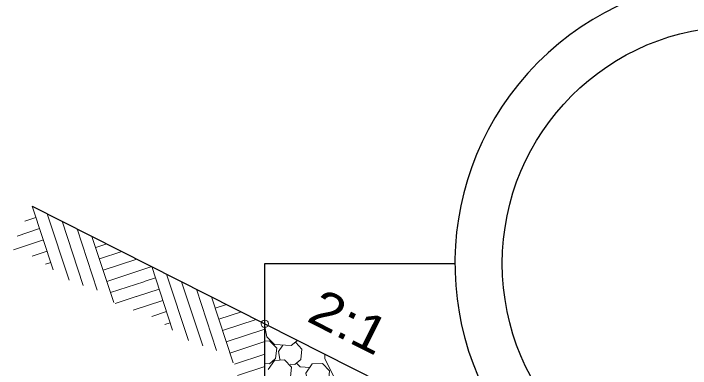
# Model space of a CAD drawing. Extents: x 685.4 to 719.4, y 1059.8 to 1105.8.
# Drawn here: x 692.638 to 695.494, y 1078.299 to 1079.794 of the extents above; entities that cross this region are included whole.
import ezdxf

# ---------------------------------------------------------------- set-up
doc = ezdxf.new("R2010")
doc.units = 0
doc.header["$LTSCALE"] = 0.062
doc.header["$PDMODE"] = 32
doc.header["$PDSIZE"] = 0.031
doc.layers.add('1', color=7, linetype='Continuous', lineweight=13)

msp = doc.modelspace()

# ---------------------------------------------------------------- linework, layer by layer
at = {"layer": '1'}
for p, q in [((692.71692, 1078.98283), (692.80517, 1078.71458)), ((692.68508, 1078.91983), (692.7325, 1078.93542)), ((692.77992, 1078.951), (692.872, 1078.67083)), ((692.84283, 1078.91917), (692.93192, 1078.6485)), ((692.65317, 1078.85675), (692.74817, 1078.888)), ((692.906, 1078.88733), (692.99075, 1078.62942)), ((692.638, 1078.79925), (692.76375, 1078.84058)), ((692.969, 1078.8555), (693.06058, 1078.57692)), ((692.98458, 1078.80808), (693.03192, 1078.82367)), ((692.71683, 1078.77258), (692.77933, 1078.79317)), ((693.00017, 1078.76058), (693.09508, 1078.79183)), ((693.01575, 1078.71325), (693.15808, 1078.76)), ((692.77267, 1078.7385), (692.79492, 1078.74583)), ((693.03133, 1078.66583), (693.221, 1078.72825)), ((693.221, 1078.72825), (693.30925, 1078.46)), ((693.284, 1078.69642), (693.37608, 1078.41617)), ((693.18917, 1078.66525), (693.23658, 1078.68083)), ((693.04692, 1078.61842), (693.18733, 1078.66458)), ((693.34692, 1078.66458), (693.436, 1078.39392)), ((693.15733, 1078.60217), (693.25225, 1078.63325)), ((693.41008, 1078.63267), (693.49492, 1078.37483)), ((693.06642, 1078.57225), (693.1555, 1078.60142)), ((693.14225, 1078.54458), (693.26783, 1078.58592)), ((693.47308, 1078.60083), (693.56467, 1078.32225)), ((693.48867, 1078.5535), (693.536, 1078.56908)), ((693.22092, 1078.518), (693.28342, 1078.5385)), ((693.50433, 1078.506), (693.59917, 1078.53717)), ((693.51983, 1078.45867), (693.66217, 1078.50533)), ((693.27675, 1078.48383), (693.299, 1078.49108)), ((693.53542, 1078.41125), (693.69792, 1078.46458)), ((693.551, 1078.36383), (693.69792, 1078.41217)), ((693.75533, 1078.37092), (693.77367, 1078.397)), ((693.57058, 1078.31767), (693.69792, 1078.3595)), ((693.58325, 1078.26925), (693.69792, 1078.307))]:
    msp.add_line(p, q, dxfattribs=at)
at = {"layer": '1', "lineweight": 25}
for p, q in [((693.69792, 1077.09492), (693.69792, 1078.741)), ((693.69792, 1078.741), (694.50008, 1078.741))]:
    msp.add_line(p, q, dxfattribs=at)
msp.add_lwpolyline([(692.71692, 1078.98283), (693.69792, 1078.48725), (695.1745, 1077.7415)], dxfattribs=at)
at = {"layer": '1'}
for points in [[(693.69792, 1078.47792), (693.69967, 1078.47608), (693.69792, 1078.45867)], [(693.83667, 1078.41725), (693.81, 1078.39508), (693.73933, 1078.40017), (693.70608, 1078.43242), (693.69792, 1078.47442)], [(693.69792, 1078.41367), (693.71842, 1078.41483), (693.74825, 1078.38392), (693.74392, 1078.34058), (693.71742, 1078.3185), (693.69792, 1078.31992)], [(693.8285, 1078.40817), (693.855, 1078.38067), (693.85067, 1078.33733), (693.82417, 1078.31525), (693.80492, 1078.31667)], [(693.76325, 1078.33625), (693.76183, 1078.33767), (693.75533, 1078.37092)], [(694.04658, 1078.21317), (693.99442, 1078.254), (693.9515, 1078.33975), (693.95117, 1078.35942)], [(693.71167, 1078.29483), (693.73858, 1078.333), (693.7815, 1078.33542), (693.81133, 1078.30458), (693.80717, 1078.26317)], [(693.889, 1078.30317), (693.84767, 1078.30617), (693.83142, 1078.32183)]]:
    msp.add_lwpolyline(points, dxfattribs=at)
msp.add_lwpolyline([(693.87158, 1078.27967), (693.8985, 1078.31783), (693.94142, 1078.32025), (693.97125, 1078.28942), (693.96692, 1078.24608), (693.94042, 1078.224), (693.898, 1078.22708), (693.87808, 1078.24642)], close=True, dxfattribs=at)
at = {"layer": '1', "lineweight": 25}
msp.add_ellipse((695.69951, 1078.74096), major_axis=(1.19944, 0), ratio=0.999895, start_param=5.5737299, end_param=10.1752, dxfattribs=at)
msp.add_ellipse((695.69951, 1078.74096), major_axis=(0.99953, 0), ratio=0.999895, dxfattribs=at)
at = {"layer": '1'}
msp.add_point((693.69792, 1078.48725), dxfattribs=at)

# ---------------------------------------------------------------- texts
at = {"layer": '1', "width": 1.15}
msp.add_text('2:1', height=0.156, rotation=333.2, dxfattribs=at).set_placement((693.86925, 1078.501))

doc.saveas('drawing.dxf')
